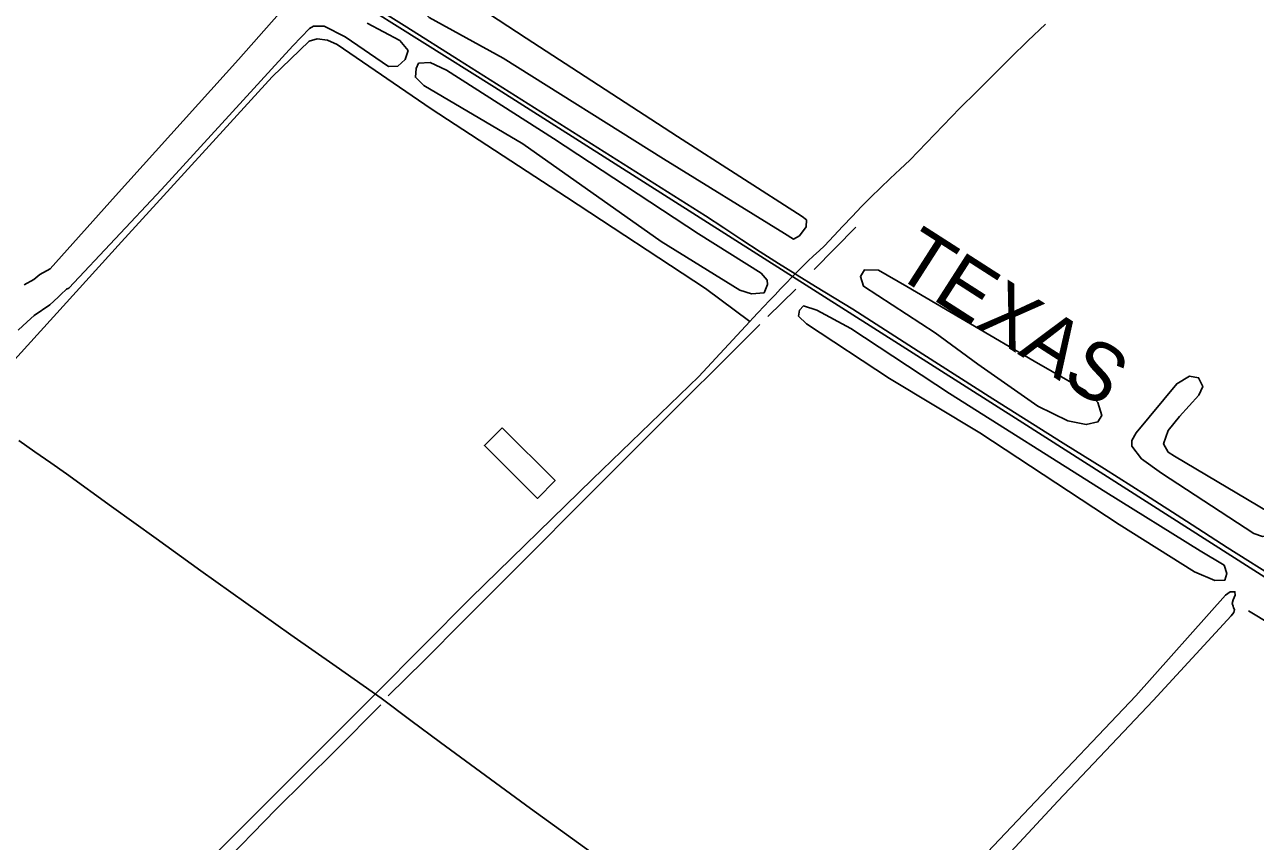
# Model space of a CAD drawing. Extents: x 3567028 to 3605064, y 510945 to 536587.
# Drawn here: x 3576780 to 3578560, y 525823 to 527003 of the extents above; entities that cross this region are included whole.
import ezdxf

# ---------------------------------------------------------------- set-up
doc = ezdxf.new("R2010")
doc.units = 0
for name, color, linetype in [('V-BLDG-OTLN', 7, 'Continuous'), ('V-DTCH-CNTR', 7, 'Continuous'), ('V-RAIL-IDEN', 7, 'Continuous'), ('V-RAIL-TRAK', 7, 'Continuous'), ('V-ROAD-CNTR', 7, 'Continuous'), ('V-SITE-VEGE', 7, 'Continuous'), ('V-TOPO-SHOR', 7, 'Continuous')]:
    doc.layers.add(name, color=color, linetype=linetype)

msp = doc.modelspace()

# ---------------------------------------------------------------- linework, layer by layer
at = {"layer": 'V-BLDG-OTLN'}
msp.add_lwpolyline([(3577470.9, 526420.4), (3577547.4, 526344.1), (3577521.8, 526318.4), (3577445.2, 526394.7)], close=True, dxfattribs=at)
at = {"layer": 'V-DTCH-CNTR'}
for points in [[(3577829, 526574.2), (3577764.9, 526621.5), (3577564, 526753.6), (3577368, 526881.4), (3577232.1, 526974), (3577218.2, 526980.5), (3577203.6, 526982.2), (3577191.6, 526978.9), (3577138.3, 526927.5), (3576920.3, 526689.1), (3576704.4, 526451.6)], [(3577287.5, 526035.8), (3577425.6, 526174.6), (3577601.3, 526346.3), (3577755, 526494.3), (3577829, 526574.2), (3577833.1, 526578.7)], [(3577598.7, 525807.6), (3577555.1, 525838.8), (3577511.6, 525870.3), (3577468.3, 525901.8), (3577425, 525933.6), (3577381.9, 525965.5), (3577338.9, 525997.6), (3577296, 526029.8), (3577230.7, 526075.5), (3577165.4, 526121.4), (3577100.3, 526167.5), (3577035.3, 526213.7), (3576970.5, 526260.2), (3576905.8, 526306.8), (3576841.2, 526353.6), (3576818.1, 526369.5), (3576795.1, 526385.6), (3576772.2, 526401.8)], [(3579234.5, 525702), (3579213.1, 525714.8), (3579191.9, 525724.7), (3579167.8, 525740), (3579141.8, 525763), (3579126.3, 525778.7), (3579115.6, 525789.6), (3579099.3, 525807.1), (3579080.9, 525824), (3579063.6, 525836.8), (3578973.6, 525897.7), (3578789, 526012), (3578549.7, 526156)], [(3577287.5, 526035.8), (3576968.4, 525716.8), (3576938.9, 525688.3), (3576909.6, 525659.6), (3576880.4, 525630.7), (3576851.3, 525601.7), (3576822.4, 525572.6), (3576793.6, 525543.3), (3576765, 525513.8), (3576736.6, 525484.2), (3576708.3, 525454.5), (3576680.1, 525424.6), (3576652.1, 525394.6), (3576624.3, 525364.4), (3576596.6, 525334.1)]]:
    msp.add_lwpolyline(points, dxfattribs=at)
at = {"layer": 'V-RAIL-TRAK'}
for points in [[(3577977.7, 526591.7), (3577950.8, 526608), (3577923.9, 526624.5), (3577897.2, 526641.1), (3577894.4, 526642.8), (3577870.5, 526657.9), (3577844, 526674.8), (3577817.5, 526692), (3577791.2, 526709.3), (3577765, 526726.7), (3577407.9, 526952.1), (3577332.9, 526999.1), (3577258.1, 527046.3), (3577183.4, 527093.7), (3577108.8, 527141.4), (3577047.7, 527180.2), (3576986.4, 527219), (3576925.1, 527257.6), (3576863.6, 527296), (3576805.2, 527332.4), (3576802.1, 527334.4), (3576770.5, 527355.1)], [(3579211.8, 525809.8), (3579135.2, 525858), (3579058.6, 525906.3), (3578982.2, 525954.9), (3578904.2, 526003.9), (3578826.4, 526053), (3578748.6, 526102.4), (3578672.2, 526150.9), (3578595.7, 526199.2), (3578519.1, 526247.4), (3578460.1, 526285.5), (3578400.9, 526323.3), (3578341.5, 526360.9), (3578282, 526398.2), (3578180.4, 526462.4), (3578079, 526526.9), (3577977.7, 526591.7)]]:
    msp.add_lwpolyline(points, dxfattribs=at)
at = {"layer": 'V-ROAD-CNTR'}
for points in [[(3571107.5, 530923.8), (3571335.7, 530779.9), (3572456, 530074.7), (3572913.2, 529784.9), (3573353.2, 529506.1), (3574011.9, 529090.4), (3574465.9, 528803.8), (3574566.4, 528736.8), (3574909.2, 528519.1), (3575756.4, 527984.9), (3576622.6, 527437), (3577459.5, 526912.7), (3578223.7, 526427.4), (3578886.3, 526005.2), (3579395.2, 525684), (3580151.7, 525207.4), (3580699, 524864.7), (3581176, 524557.8)], [(3578256.2, 527003.7), (3578231, 526979.3), (3578206.1, 526955.2), (3578181.4, 526931), (3578156.9, 526906.5), (3578132.5, 526882), (3578108.3, 526857.2), (3578084.2, 526832.3), (3578060.3, 526807.3), (3578046, 526794.1), (3578031.9, 526780.8), (3578017.9, 526767.3), (3578004, 526753.6), (3577990.3, 526739.9), (3577976.8, 526725.9), (3577963.4, 526711.9), (3577950.1, 526697.7), (3577937, 526683.4), (3577928.9, 526676.1), (3577920.8, 526668.7), (3577912.9, 526661.2), (3577905, 526653.5), (3577897.2, 526645.8), (3577894.4, 526642.8)], [(3577894.4, 526642.8), (3577889.6, 526637.9), (3577881.5, 526629.5), (3577873.4, 526621.1), (3577865.4, 526612.6), (3577857.3, 526604.2), (3577849.2, 526595.7), (3577841.1, 526587.2), (3577833.1, 526578.7)]]:
    msp.add_lwpolyline(points, dxfattribs=at)
at = {"layer": 'V-SITE-VEGE'}
for p, q in [((3577089.7, 526952.5), (3577148.2, 527019.2)), ((3577198.1, 527000.8), (3577192.4, 526997.5)), ((3577213.4, 527000.6), (3577198.1, 527000.8)), ((3577243.9, 526985.4), (3577213.4, 527000.6)), ((3577275.7, 527005), (3577322.7, 526979.8)), ((3577192.4, 526997.5), (3577168.3, 526972.1)), ((3577306.6, 526942.3), (3577243.9, 526985.4)), ((3577168.3, 526972.1), (3576978.1, 526764.7)), ((3577322.7, 526979.8), (3577335, 526965.6)), ((3577335, 526965.6), (3577330.6, 526952.4)), ((3576911.6, 526755.4), (3577089.7, 526952.5)), ((3577330.6, 526952.4), (3577319.9, 526942.8)), ((3577319.9, 526942.8), (3577306.6, 526942.3)), ((3576817.4, 526650.3), (3576911.6, 526755.4)), ((3576978.1, 526764.7), (3576844.3, 526621.9)), ((3576802.5, 526641.9), (3576817.4, 526650.3)), ((3576779.8, 526627.1), (3576793.7, 526634.7)), ((3576793.7, 526634.7), (3576802.5, 526641.9)), ((3576829.1, 526609.1), (3576816.8, 526598)), ((3576832.7, 526613), (3576829.1, 526609.1)), ((3576840.9, 526620.8), (3576832.7, 526613)), ((3576844.3, 526621.9), (3576840.9, 526620.8)), ((3576816.8, 526598), (3576794.1, 526582.6)), ((3576784.1, 526573.7), (3576771.2, 526561.5)), ((3576794.1, 526582.6), (3576784.1, 526573.7))]:
    msp.add_line(p, q, dxfattribs=at)
for points in [[(3577878.9, 526701), (3577704.2, 526808.8), (3577472.3, 526954.7), (3577365.2, 527013.2), (3577354.9, 527024.5), (3577358.7, 527044.7), (3577371.5, 527055), (3577385.5, 527056.1), (3577410.4, 527045.9), (3577505.6, 526983.4), (3577724.4, 526841.3), (3577904.5, 526725.7), (3577910.7, 526720.7), (3577910.5, 526710.9), (3577900.5, 526697.8), (3577892, 526693.1)], [(3577500.8, 526830.6), (3577357.8, 526914.9), (3577345.5, 526927), (3577346.4, 526939.5), (3577350, 526947.1), (3577366.8, 526948.2), (3577390.3, 526937.3), (3577544.9, 526838.2), (3577754.7, 526700.4), (3577845.1, 526643.6), (3577854, 526633.7), (3577854.6, 526627.4), (3577849.5, 526615.6), (3577831.3, 526613.9), (3577814.6, 526619.1), (3577700.7, 526689.5)], [(3578096.9, 526557.4), (3577993.4, 526624.9), (3577988.8, 526639), (3577994.6, 526648.6), (3578014.8, 526648.3), (3578055.6, 526624.5), (3578240, 526516.5), (3578314.6, 526473.9), (3578331.8, 526456.9), (3578337.7, 526437.9), (3578332, 526428.9), (3578315.2, 526425.1), (3578288.7, 526430.4), (3578245.1, 526451.5), (3578158.3, 526512.4)], [(3578030.8, 526491.6), (3577910.8, 526570.6), (3577899.1, 526581.9), (3577900.7, 526590.3), (3577906.4, 526596.5), (3577925.8, 526590.5), (3577974.9, 526563.8), (3578117.7, 526469.8), (3578343.4, 526327.5), (3578480.1, 526242.7), (3578514.6, 526221.8), (3578518.6, 526209.9), (3578515.6, 526200.2), (3578501, 526199.7), (3578471.9, 526212.1), (3578362.8, 526280.4), (3578161.4, 526413.2)], [(3578594.7, 526289.5), (3578602.3, 526283.8), (3578595.2, 526274.1), (3578583.9, 526266), (3578569.8, 526263.4), (3578557.4, 526267.8), (3578424.2, 526354.7), (3578395.2, 526375.5), (3578380.9, 526393.9), (3578381.1, 526402.2), (3578387.5, 526413.3), (3578446.1, 526484.1), (3578464.4, 526495), (3578477.6, 526492.6), (3578483.7, 526480), (3578477.9, 526467.5), (3578450.1, 526436.6), (3578433.7, 526416.6), (3578427, 526397.2), (3578433.8, 526385.2), (3578442.8, 526379.5)]]:
    msp.add_lwpolyline(points, close=True, dxfattribs=at)
at = {"layer": 'V-TOPO-SHOR'}
for p, q in [((3577982.2, 526710.2), (3577921.8, 526649.1)), ((3577895.4, 526620.9), (3577854.9, 526581.2)), ((3578528.8, 526153.4), (3578524.5, 526148.6))]:
    msp.add_line(p, q, dxfattribs=at)
for points in [[(3577843.5, 526569.5), (3577677.9, 526404.9), (3577415.4, 526142.1)], [(3578085.8, 525715.8), (3578233.2, 525871), (3578387, 526033), (3578516.7, 526178.7), (3578523.1, 526183.5), (3578530.1, 526183.4), (3578530.7, 526178.5), (3578527.7, 526171.6), (3578526.3, 526166.7), (3578527.6, 526162.5), (3578528.2, 526160.4), (3578529.6, 526157.6), (3578528.8, 526153.4)], [(3578524.5, 526148.6), (3578412, 526026.3), (3578273.9, 525880.7), (3578107.2, 525701.4)], [(3577415.4, 526142.1), (3577357.9, 526084.3), (3577305.9, 526033)], [(3577295.2, 526020), (3577229.3, 525953.5), (3577143.7, 525868.6), (3577060.4, 525783.1), (3576949.1, 525671.6), (3576843.7, 525567.1), (3576735.3, 525459.1), (3576655.6, 525375.3), (3576620.8, 525334.1), (3576611.8, 525323.1), (3576601.6, 525313.9), (3576595.7, 525311.7)]]:
    msp.add_lwpolyline(points, dxfattribs=at)

# ---------------------------------------------------------------- texts
at = {"layer": 'V-RAIL-IDEN'}
msp.add_text('TEXAS', height=83, rotation=327.3378, dxfattribs=at).set_placement((3578033.3, 526644))

doc.saveas('drawing.dxf')
